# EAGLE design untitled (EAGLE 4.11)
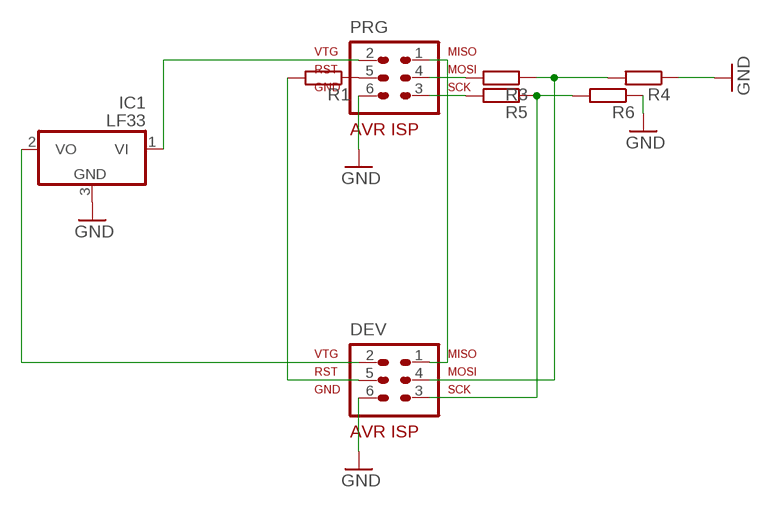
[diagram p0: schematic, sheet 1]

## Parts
DEV  AVR-ISP-6  [AVR-ISP-6]
IC1  LF33  7805DT  [TO252]
PRG  AVR-ISP-6  [AVR-ISP-6]
R1  R-EU_0204/7  [0204/7]
R3  R-EU_0204/7  [0204/7]
R4  R-EU_0204/7  [0204/7]
R5  R-EU_0204/7  [0204/7]
R6  R-EU_0204/7  [0204/7]

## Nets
GND: DEV.6 IC1.3(GND) PRG.6 R4.1 R6.1
N$1: IC1.1(VI) PRG.2
N$2: DEV.2 IC1.2(VO)
N$3: PRG.5 R1.1
N$4: PRG.4 R3.2
N$5: PRG.3 R5.2
N$6: DEV.4 R3.1 R4.2
N$7: DEV.3 R5.1 R6.2
N$8: DEV.1 PRG.1
N$9: DEV.5 R1.2

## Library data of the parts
DEV PRG = atmel:AVR-ISP-6: AVR ISP-6 Serial Programming Header
IC1 = HuB:78*: Positive VOLTAGE REGULATOR
R1 R3-R6 = rcl:R-EU_: RESISTOR, European symbol

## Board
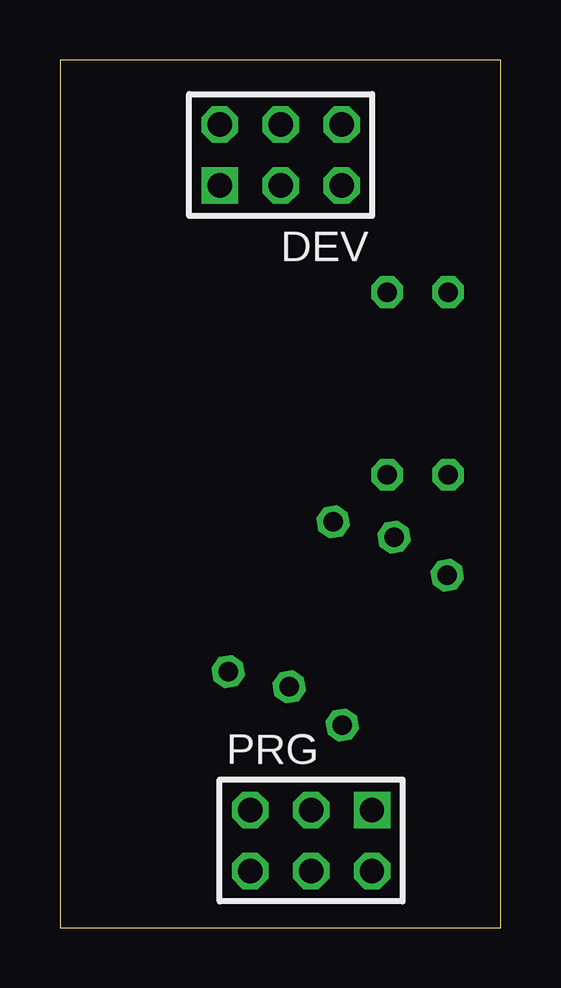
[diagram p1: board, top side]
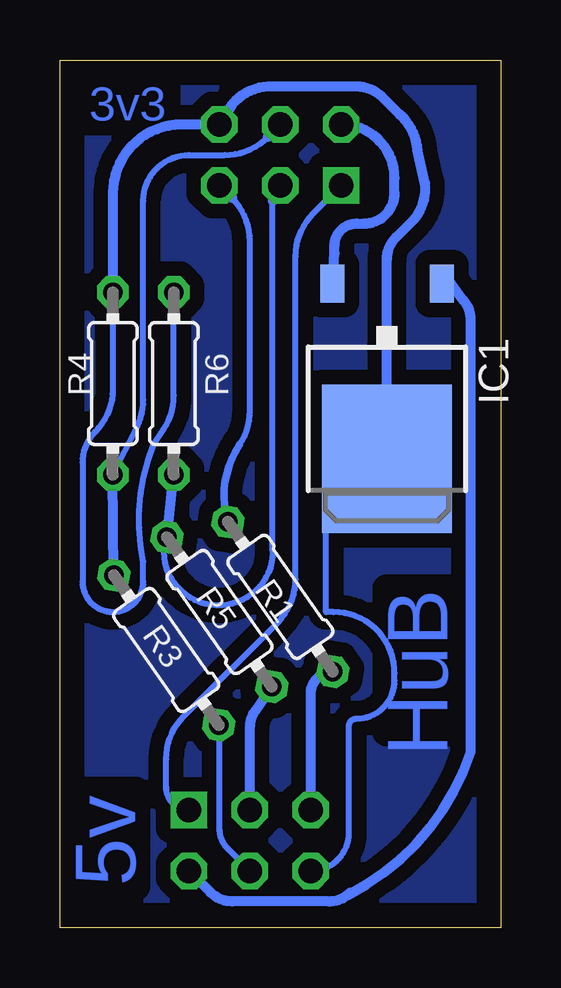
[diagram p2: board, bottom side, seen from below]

Size 18.39 x 36.18 mm. Coordinates in mm from the lower left corner, seen from the top.
Outline: 0,0 18.39,0 18.39,36.18 0,36.18 0,0
Copper layers (1*16): Top 0.035mm / dielectric 1.5mm / Bottom 0.035mm
Design rules "default": minimum track width 10mil, minimum drill 24mil, track to track 8mil, track to pad 8mil, pad to pad 8mil, via to via 8mil, smd to smd 8mil, copper to edge 40mil, drill to drill 8mil, minimum pad ring 10mil, minimum via ring 8mil, stop-mask expansion 4mil, vias tented up to drill 0mil, thermal gap 10mil

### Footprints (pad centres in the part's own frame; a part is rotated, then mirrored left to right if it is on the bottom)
AVR-ISP-6 = drill 1.016 square: 1 -2.54,-1.27 | drill 1.016 octagon: 2 -2.54,1.27; 3 0,-1.27; 4 0,1.27; 5 2.54,-1.27; 6 2.54,1.27
TO252 = smd 1 x 1.6: 1 -2.28,-4.8; 2 2.28,-4.8 | smd 5.4 x 6.2: 3 0,2.5
0204/7 = drill 0.813 octagon: 1 -3.81,0; 2 3.81,0

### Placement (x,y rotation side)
DEV  9.2,32.22 0 top
IC1  4.76,22.06 180 bottom
PRG  10.47,3.65 180 top
R1  9.2,13.8 125 bottom
R3  13.96,11.58 305 bottom
R4  16.19,22.7 270 bottom
R5  11.74,13.17 305 bottom
R6  13.65,22.7 270 bottom

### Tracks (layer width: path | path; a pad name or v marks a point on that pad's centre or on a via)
GND
  Bottom 0.254: R4.1 16.19,22.48 arc45 16.93,20.68 arc-45 17.46,19.41 17.46,14.44 arc-180 14.92,14.44 14.92,15.26 arc34 14.49,20.16 14.07,20.79 arc-34 13.65,22.19 R6.1 | IC1.3 4.76,17.3 6.66,17.3 arc-90 7.3,16.66 7.3,13.17 6.98,13.17 arc90 4.44,10.63 4.44,10.31 arc90 6.03,8.72 arc-90 6.34,8.41 6.34,3.96 arc90 PRG.6
  Bottom 0.406: IC1.3 4.76,27.88 arc45 4.39,28.78 3.6,29.57 arc-45 3.17,31.05 3.49,32.44 arc-45 4.23,33.92 4.97,34.65 arc-45 6.13,35.08 9.74,35.08 arc-45 11.22,34.33 DEV.6 13.33,33.49 arc-90 16.19,30.63 R4.1
N$1
  Bottom 0.406: IC1.1 2.48,27.4 1.64,26.24 arc45 1.27,25.34 1.27,7.35 arc45 6.4,1.37 6.29,1.48 arc45 7.19,1.11 11.22,1.11 arc45 12.11,1.48 PRG.2
N$2
  Bottom 0.406: IC1.2 6.94,28.13 6.94,28.45 arc90 6.03,29.36 5.71,29.36 arc-90 4.44,30.63 4.44,31.27 arc-90 DEV.2
N$3
  Bottom 0.406: R1.1 arc-90 7.93,9.77 PRG.5
N$4
  Bottom 0.254: 11.74,8.72 11.74,4.17 arc-45 11.37,3.27 PRG.4
  Bottom 0.406: 11.74,8.72 R3.2
N$5
  Bottom 0.406: R5.2 10.25,9.05 arc-35 10.47,8.33 PRG.3
N$6
  Bottom 0.254: R4.2 15.19,20.89 arc-27 14.92,22.02 14.92,30.32 arc90 13.01,32.22 11.52,32.22 arc-45 9.73,32.96
  Bottom 0.406: R3.1 R4.2 | 9.73,32.96 DEV.4
N$7
  Bottom 0.254: 9.52,30.32 9.52,15.71 arc196 13.96,16.34
  Bottom 0.406: R6.2 R5.1 13.96,16.34 | 9.52,30.32 DEV.3
N$8
  Bottom 0.254: DEV.1 7.82,29.79 arc-45 8.57,27.99 8.57,14.54 arc45 9.31,12.74 13.22,8.83 arc-45 13.96,7.04 13.96,5.87 arc-90 PRG.1
N$9
  Bottom 0.254: 10.9,20.15 arc-34 10.47,21.56 10.47,28.63 arc-45 11.22,30.42
  Bottom 0.305: R1.2 11.42,16.98 arc49 10.9,20.15
  Bottom 0.406: 11.22,30.42 DEV.5
N$10
  pour Bottom (isolate 0.61): -0.32,36.67 -0.32,-0.8 18.41,-0.8 18.41,36.98 -0.01,36.98

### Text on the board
Bottom: 3v3 | HuB | 5v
